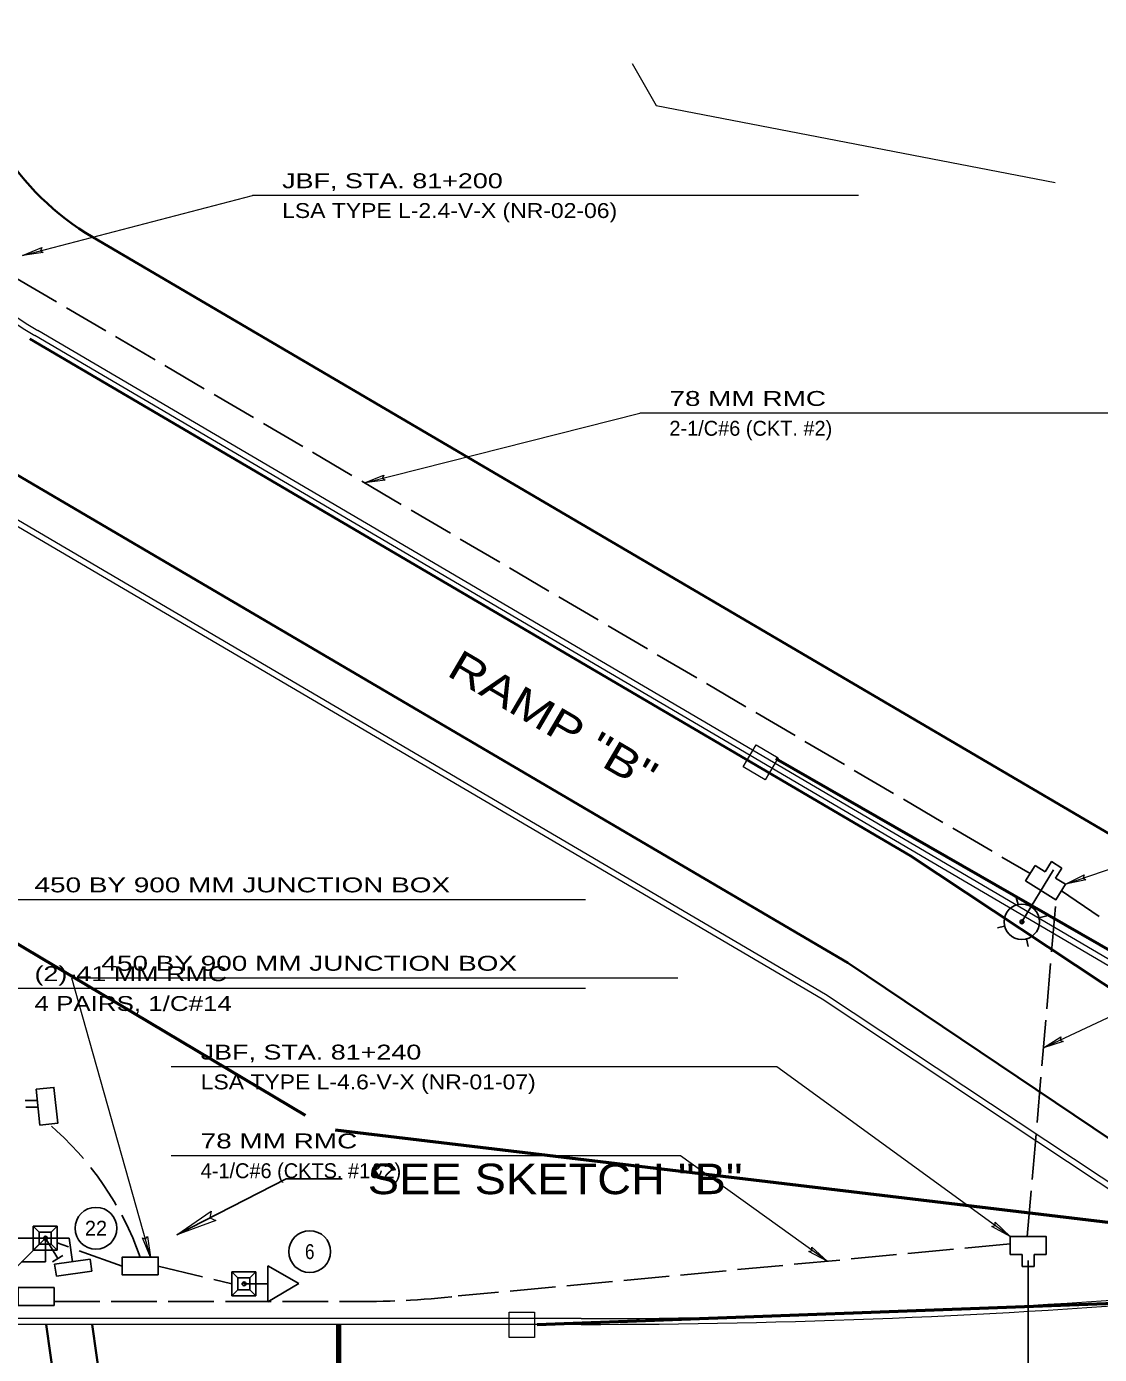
# Model space of a CAD drawing. Extents: x 168203 to 169863, y 223196 to 223870.
# Drawn here: x 168367.9 to 168410.2, y 223652.3 to 223704.6 of the extents above; entities that cross this region are included whole.
import ezdxf
from ezdxf.enums import TextEntityAlignment as Align

# ---------------------------------------------------------------- set-up
doc = ezdxf.new("R2010")
doc.units = 0
doc.header["$LTSCALE"] = 0.3
doc.header["$PDMODE"] = 32
doc.header["$PDSIZE"] = 0.15
doc.linetypes.add('LONG_DASH_SHORT_DASH', pattern=[9.9, 6, -1.2, 1.5, -1.2])
doc.linetypes.add('LONG_DASHED', pattern=[7.5, 6, -1.5])
for name, color, linetype, lineweight in [('1', 7, 'Continuous', 13), ('11', 7, 'Continuous', 13), ('23', 7, 'Continuous', 25), ('3', 7, 'Continuous', 25), ('31', 7, 'Continuous', 25), ('36', 7, 'Continuous', 35), ('5', 7, 'Continuous', 25), ('7', 7, 'Continuous', 25), ('9', 7, 'Continuous', 13)]:
    doc.layers.add(name, color=color, linetype=linetype, lineweight=lineweight)

msp = doc.modelspace()

# ---------------------------------------------------------------- linework, layer by layer
at = {"layer": '1', "lineweight": 35}
msp.add_line((168419.4337, 223667.6033), (168370.5425, 223696.3139), dxfattribs=at)
at = {"layer": '1'}
for p, q in [((168417.0333, 223663.7944), (168368.2637, 223692.4336)), ((168417.1498, 223663.9927), (168368.3802, 223692.6319)), ((168363.5687, 223687.27), (168399.2919, 223666.2921)), ((168363.6851, 223687.4684), (168399.4139, 223666.4872)), ((168399.2919, 223666.2921), (168414.6088, 223656.1381)), ((168399.4139, 223666.4872), (168414.7358, 223656.3299)), ((168389.7958, 223653.6976), (168366.9691, 223653.6976)), ((168389.7958, 223653.4676), (168366.9691, 223653.4676))]:
    msp.add_line(p, q, dxfattribs=at)
for points in [[(168396.1792, 223675.4397), (168396.6872, 223676.3046), (168397.552, 223675.7967), (168397.0441, 223674.9318)], [(168386.9482, 223652.949), (168386.9482, 223653.952), (168387.9512, 223653.952), (168387.9512, 223652.949)]]:
    msp.add_lwpolyline(points, close=True, dxfattribs=at)
at = {"layer": '1', "lineweight": 35}
msp.add_arc((168375.8594, 223705.3683), 10.5001, 184.13349, 239.57769, dxfattribs=at)
at = {"layer": '1'}
for centre, radius, start, end in [((168375.8594, 223705.3683), 15, 184.13349, 239.57703), ((168375.8594, 223705.3683), 14.77, 184.13349, 239.57703), ((168389.7956, 223953.4676), 299.77, 270.00005, 274.68735), ((168389.7956, 223953.4676), 300, 270.00005, 274.68735)]:
    msp.add_arc(centre, radius, start, end, dxfattribs=at)
at = {"layer": '11'}
for p, q in [((168367.7738, 223695.5936), (168376.8432, 223697.9525)), ((168400.7167, 223697.9525), (168376.8432, 223697.9525)), ((168381.2533, 223686.6332), (168392.1017, 223689.373)), ((168415.9752, 223689.373), (168392.1017, 223689.373)), ((168408.8764, 223670.8103), (168419.999, 223674.6785)), ((168408.0024, 223664.3628), (168419.999, 223669.9988)), ((168372.8249, 223656.1245), (168369.7218, 223667.116)), ((168393.5953, 223667.116), (168369.7218, 223667.116)), ((168397.5067, 223663.616), (168373.6332, 223663.616)), ((168406.6999, 223656.9345), (168397.5067, 223663.616)), ((168393.7024, 223660.116), (168373.6332, 223660.116)), ((168399.4832, 223655.9595), (168393.7024, 223660.116))]:
    msp.add_line(p, q, dxfattribs=at)
for points in [[(168368.5859, 223695.7021), (168367.7738, 223695.5936), (168368.5336, 223695.9032), (168368.4821, 223695.7778)], [(168382.0662, 223686.736), (168381.2533, 223686.6332), (168382.0153, 223686.9374), (168381.9629, 223686.8124)], [(168409.6772, 223670.9836), (168408.8764, 223670.8103), (168409.609, 223671.1798), (168409.5677, 223671.0507)], [(168408.7808, 223664.6187), (168408.0024, 223664.3628), (168408.6924, 223664.8067), (168408.6648, 223664.674)], [(168406.1004, 223657.4931), (168406.6999, 223656.9345), (168405.9783, 223657.325), (168406.1078, 223657.3648)], [(168372.6996, 223656.9342), (168372.8249, 223656.1245), (168372.4996, 223656.8778), (168372.626, 223656.8289)], [(168398.8809, 223656.515), (168399.4832, 223655.9595), (168398.7596, 223656.3463), (168398.889, 223656.3868)]]:
    msp.add_lwpolyline(points, close=True, dxfattribs=at)
at = {"layer": '23', "lineweight": 53}
for p, q in [((168397.459, 223675.7705), (168426.3587, 223659.1545)), ((168363.59, 223670.8389), (168378.9117, 223661.7152)), ((168380.0972, 223661.1384), (168422.0981, 223656.1092)), ((168388.052, 223653.4671), (168412.6271, 223654.3671))]:
    msp.add_line(p, q, dxfattribs=at)
at = {"layer": '23', "lineweight": 13}
msp.add_lwpolyline([(168391.8032, 223703.15), (168392.7497, 223701.5053), (168408.4668, 223698.4649)], dxfattribs=at)
at = {"layer": '3'}
for p, q in [((168368.1992, 223657.3375), (168368.4341, 223657.1025)), ((168369.1389, 223657.3375), (168368.904, 223657.1025)), ((168368.1992, 223656.3977), (168368.4341, 223656.6327)), ((168369.1389, 223656.3977), (168368.904, 223656.6327)), ((168376.0272, 223655.5375), (168376.2621, 223655.3025)), ((168376.9669, 223655.5375), (168376.732, 223655.3025)), ((168376.0272, 223654.5977), (168376.2621, 223654.8327)), ((168376.9669, 223654.5977), (168376.732, 223654.8327))]:
    msp.add_line(p, q, dxfattribs=at)
for points in [[(168368.1992, 223657.3375), (168369.1389, 223657.3375), (168369.1389, 223656.3977), (168368.1992, 223656.3977)], [(168368.4341, 223657.1025), (168368.904, 223657.1025), (168368.904, 223656.6327), (168368.4341, 223656.6327)], [(168376.0272, 223655.5375), (168376.9669, 223655.5375), (168376.9669, 223654.5977), (168376.0272, 223654.5977)], [(168376.2621, 223655.3025), (168376.732, 223655.3025), (168376.732, 223654.8327), (168376.2621, 223654.8327)]]:
    msp.add_lwpolyline(points, close=True, dxfattribs=at)
for p in [(168368.6781, 223656.8676), (168376.5061, 223655.0676)]:
    msp.add_point(p, dxfattribs=at)
at = {"layer": '31'}
for p, q in [((168408.406, 223671.3798), (168407.1576, 223669.3301)), ((168368.6781, 223656.8676), (168356.4781, 223656.8676)), ((168368.6781, 223656.8676), (168364.3648, 223652.5542)), ((168368.6781, 223656.8676), (168368.6781, 223655.9278)), ((168369.6179, 223656.8676), (168368.6781, 223656.8676)), ((168368.6781, 223656.8676), (168369.1665, 223656.0647)), ((168369.6179, 223656.8676), (168369.7512, 223655.9373)), ((168368.6781, 223655.9278), (168367.7383, 223655.9278)), ((168369.3672, 223656.1868), (168368.958, 223655.9379)), ((168407.4002, 223655.9857), (168407.4002, 223651.3857)), ((168376.5061, 223655.0676), (168377.4459, 223655.0676))]:
    msp.add_line(p, q, dxfattribs=at)
at = {"layer": '31', "linetype": 'LONG_DASH_SHORT_DASH'}
for points in [[(168369.1112, 223655.371), (168370.5155, 223655.5722), (168370.4489, 223656.0373), (168369.0445, 223655.836)], [(168378.6657, 223655.0857), (168377.4459, 223655.7724), (168377.4459, 223655.0676), (168377.4459, 223654.3628)]]:
    msp.add_lwpolyline(points, close=True, dxfattribs=at)
at = {"layer": '31'}
for centre in [(168370.6726, 223657.2577), (168379.0954, 223656.3366)]:
    msp.add_circle(centre, 0.8236, dxfattribs=at)
at = {"layer": '36'}
for p, q in [((168368.071, 223692.3059), (168402.7689, 223671.93)), ((168365.5999, 223688.0978), (168400.2978, 223667.7219)), ((168402.7689, 223671.93), (168417.9879, 223661.8409)), ((168400.2978, 223667.7219), (168415.5046, 223657.4883)), ((168374.0279, 223615.7265), (168368.7066, 223653.4676)), ((168375.8367, 223615.7899), (168370.5243, 223653.4676))]:
    msp.add_line(p, q, dxfattribs=at)
at = {"layer": '36', "lineweight": 80}
msp.add_line((168380.2469, 223634.5676), (168380.2468, 223653.4676), dxfattribs=at)
at = {"layer": '5', "linetype": 'LONG_DASHED'}
for p, q in [((168367.5664, 223694.67), (168407.4793, 223671.2335)), ((168407.3707, 223656.9345), (168408.4991, 223670.2042)), ((168354.3859, 223662.0559), (168368.3631, 223662.2946)), ((168354.4049, 223661.7919), (168368.3905, 223662.0308)), ((168371.7071, 223655.7676), (168369.1389, 223656.679)), ((168406.6999, 223656.6401), (168384.9476, 223654.5887)), ((168373.1258, 223655.7676), (168376.0272, 223655.0687)), ((168369.0214, 223654.3768), (168380.6473, 223654.3768))]:
    msp.add_line(p, q, dxfattribs=at)
at = {"layer": '5'}
for p, q in [((168407.6796, 223671.5553), (168408.0785, 223671.3069)), ((168408.7334, 223671.4527), (168408.4851, 223671.0539)), ((168408.4851, 223671.0539), (168408.8764, 223670.8103)), ((168407.1608, 223656.2206), (168406.6999, 223656.2206)), ((168407.1608, 223655.7508), (168407.1608, 223656.2206)), ((168408.1096, 223656.2206), (168407.6397, 223656.2206))]:
    msp.add_line(p, q, dxfattribs=at)
for points in [[(168408.8764, 223670.8103), (168408.4991, 223670.2042), (168407.3024, 223670.9492), (168407.6796, 223671.5553)], [(168408.0785, 223671.3069), (168408.3268, 223671.7058), (168408.7334, 223671.4527)], [(168406.6999, 223656.2206), (168406.6999, 223656.9345), (168408.1096, 223656.9345), (168408.1096, 223656.2206)], [(168407.6397, 223656.2206), (168407.6397, 223655.7508), (168407.1608, 223655.7508)]]:
    msp.add_lwpolyline(points, dxfattribs=at)
for points in [[(168368.4638, 223661.3252), (168368.3172, 223662.7363), (168369.0182, 223662.8091), (168369.1648, 223661.398)], [(168373.1258, 223655.4197), (168371.7071, 223655.4197), (168371.7071, 223656.1245), (168373.1258, 223656.1245)], [(168369.0214, 223654.2176), (168367.6027, 223654.2176), (168367.6027, 223654.9224), (168369.0214, 223654.9224)]]:
    msp.add_lwpolyline(points, close=True, dxfattribs=at)
at = {"layer": '5', "linetype": 'LONG_DASHED'}
for centre, radius, start, end in [((168468.0083, 223756.6858), 104.5726, 235.45741, 251.92502), ((168360.8437, 223652.0298), 12.2757, 19.48491, 49.48362), ((168381.2447, 223685.9948), 31.6236, 268.91761, 276.7244)]:
    msp.add_arc(centre, radius, start, end, dxfattribs=at)
at = {"layer": '7'}
for p, q in [((168406.93, 223670.2939), (168407.0041, 223670.0161)), ((168408.1387, 223669.5684), (168407.8283, 223669.493)), ((168406.4746, 223669.1641), (168406.1968, 223669.0901)), ((168407.333, 223668.6625), (168407.4007, 223668.3568))]:
    msp.add_line(p, q, dxfattribs=at)
msp.add_circle((168407.1538, 223669.3324), 0.6965, dxfattribs=at)
msp.add_point((168407.1576, 223669.3301), dxfattribs=at)
at = {"layer": '9'}
for p, q in [((168389.9644, 223670.2051), (168367.0853, 223670.2051)), ((168389.9644, 223666.7051), (168367.0853, 223666.7051))]:
    msp.add_line(p, q, dxfattribs=at)
at = {"layer": '9', "lineweight": 25}
for p, q in [((168373.8561, 223656.997), (168378.1708, 223659.2014)), ((168378.1708, 223659.2014), (168380.368, 223659.2014))]:
    msp.add_line(p, q, dxfattribs=at)
at = {"layer": '9'}
msp.add_lwpolyline([(168375.3951, 223657.56), (168373.8561, 223656.997), (168375.2059, 223657.9302), (168375.1597, 223657.663)], close=True, dxfattribs=at)

# ---------------------------------------------------------------- texts
at = {"layer": '1', "width": 1.25}
msp.add_text('RAMP "B"', height=1.202, rotation=329.577, dxfattribs=at).set_placement((168388.3819, 223676.7554), align=Align.CENTER)
at = {"layer": '11'}
for s, width, p in [('JBF, STA. 81+200            ', 1.35, (168378.0089, 223698.2417)), ('LSA TYPE L-2.4-V-X (NR-02-06)          ', 1.15, (168378.0089, 223697.067)), ('78 MM RMC                            ', 1.4, (168393.2674, 223689.6622)), ('450 BY 900 MM JUNCTION BOX           ', 1.4, (168370.8875, 223667.4052)), ('JBF, STA. 81+240                 ', 1.35, (168374.7989, 223663.9052)), ('LSA TYPE L-4.6-V-X (NR-01-07)          ', 1.15, (168374.7989, 223662.7305)), ('78 MM RMC                            ', 1.4, (168374.7989, 223660.4052))]:
    msp.add_text(s, height=0.5873, dxfattribs=dict(at, width=width)).set_placement(p)
for s, p in [('2-1/C#6 (CKT. #2)                    ', (168393.2674, 223688.4875)), ('4-1/C#6 (CKTS. #1&2)                    ', (168374.7989, 223659.2305))]:
    msp.add_text(s, height=0.5873, dxfattribs=at).set_placement(p)
at = {"layer": '31'}
msp.add_text('22', height=0.5873, dxfattribs=at).set_placement((168370.6727, 223656.9641), align=Align.CENTER)
at = {"layer": '31', "width": 0.85}
msp.add_text('6', height=0.5873, dxfattribs=at).set_placement((168379.0954, 223656.043), align=Align.CENTER)
at = {"layer": '9'}
for s, width, p in [('450 BY 900 MM JUNCTION BOX           ', 1.4, (168368.251, 223670.4943)), ('(2)-41 MM RMC                        ', 1.35, (168368.251, 223666.9943)), ('4 PAIRS, 1/C#14                      ', 1.3, (168368.251, 223665.8196))]:
    msp.add_text(s, height=0.5873, dxfattribs=dict(at, width=width)).set_placement(p)
at = {"layer": '9', "width": 1.15}
msp.add_text('SEE SKETCH "B"', height=1.202, dxfattribs=at).set_placement((168388.7656, 223658.6005), align=Align.CENTER)

doc.saveas('drawing.dxf')
